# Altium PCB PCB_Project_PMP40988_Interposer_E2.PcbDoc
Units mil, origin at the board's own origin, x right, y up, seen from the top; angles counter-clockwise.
Board outline 2755.91 x 2165.35 mil, 2 copper layers (Top Layer, Bottom Layer), stack 62 mil thick; 7 components, 34 nets, 208 pads, 25 vias.
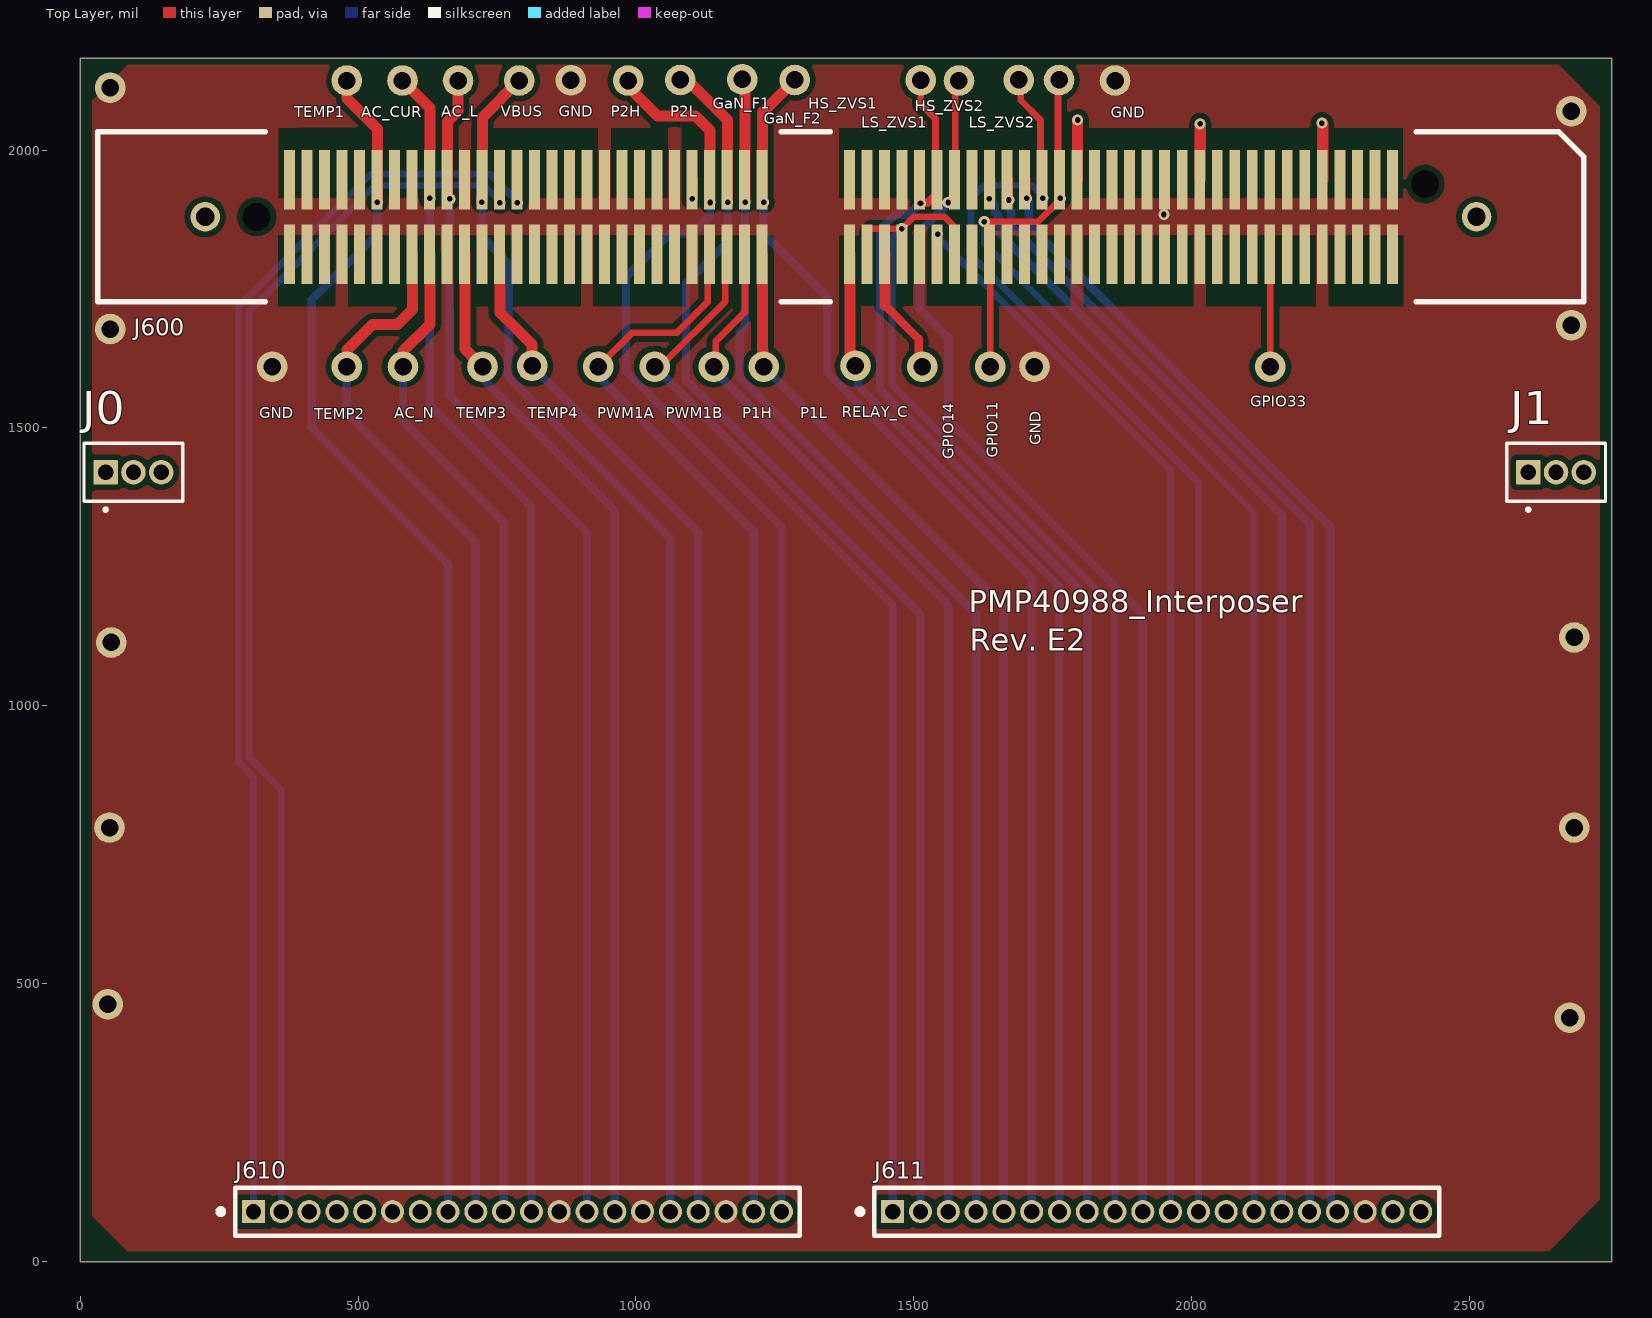
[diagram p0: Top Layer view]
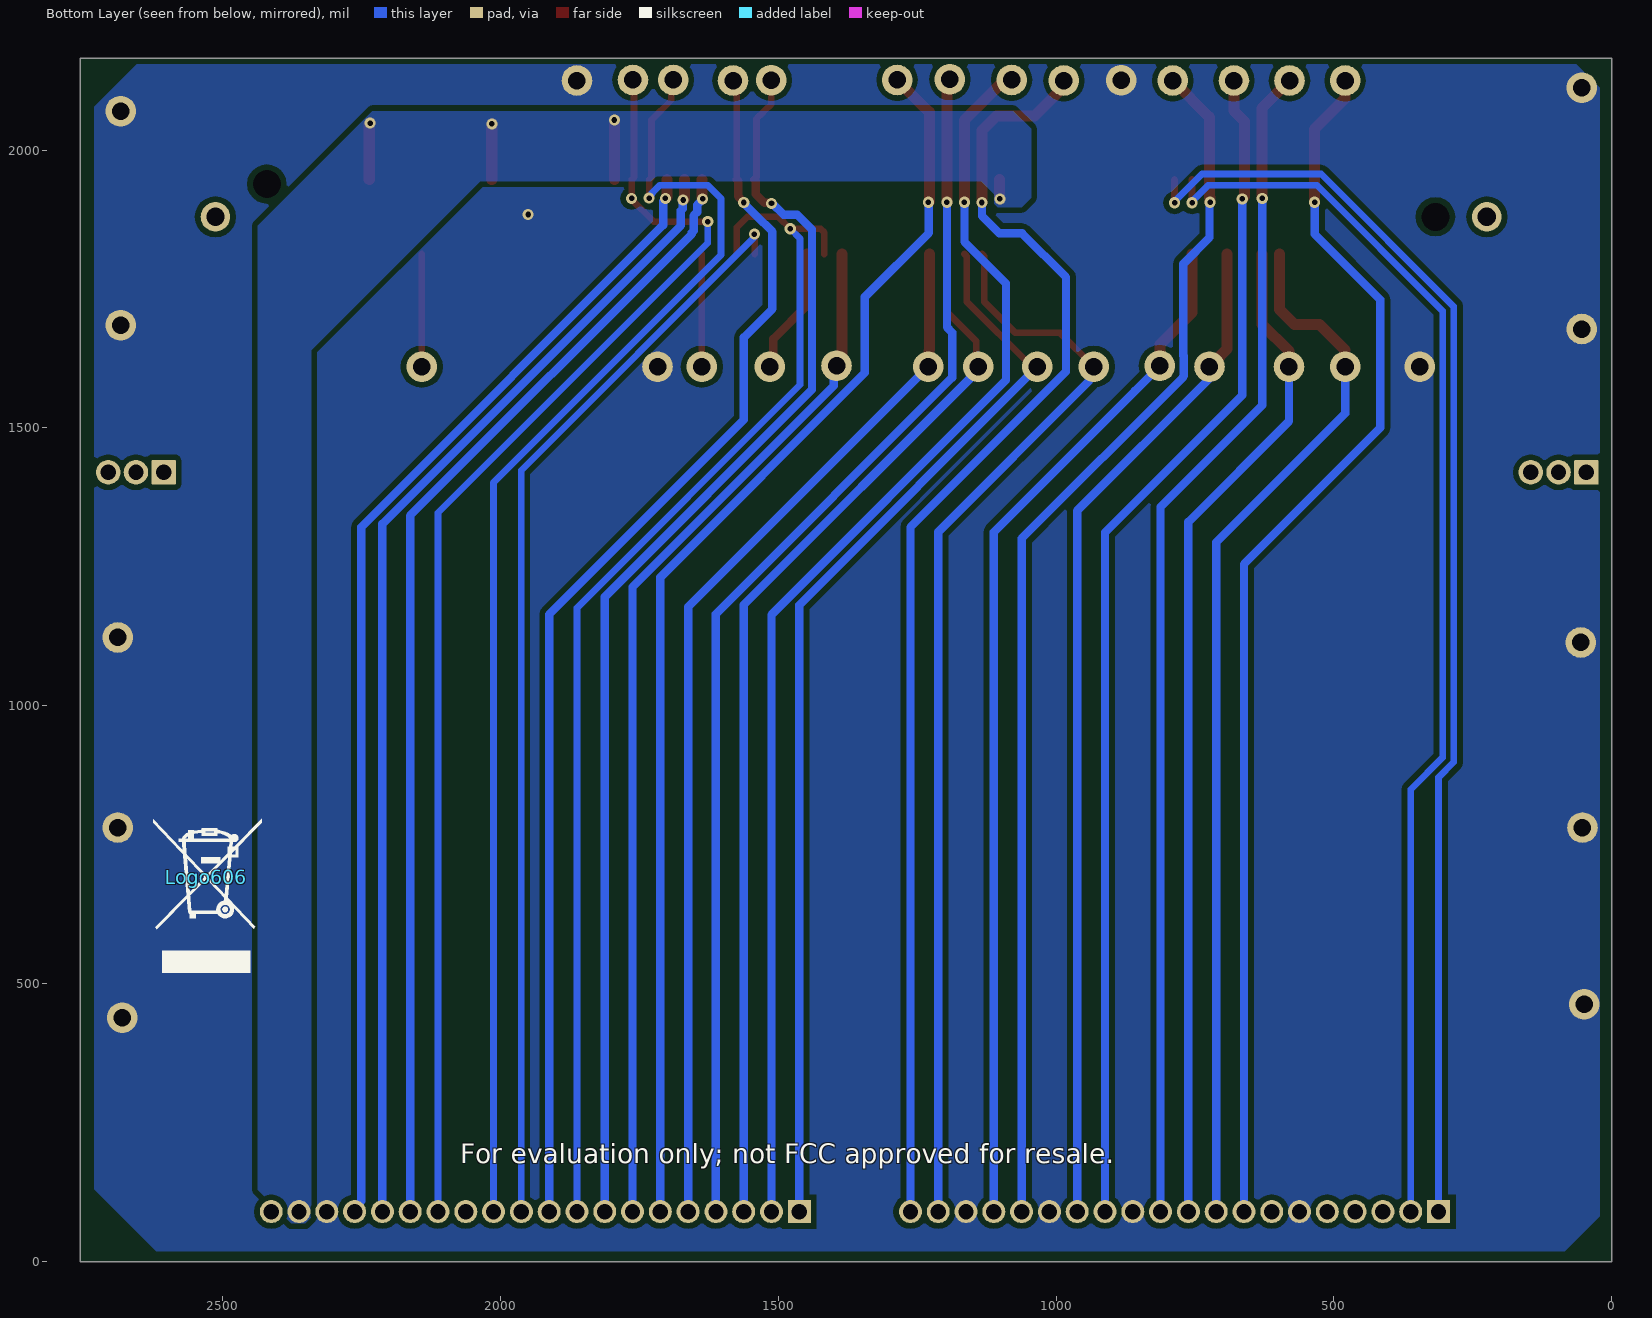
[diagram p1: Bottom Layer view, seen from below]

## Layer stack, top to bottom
Top Solder: solder mask 0.4, Solder Resist, Dk 3.5
Top Layer: signal copper 1.4
Dielectric1: core 59.2, FR-4 High Tg, Dk 4.8
Bottom Layer: signal copper 1.4
Bottom Solder: solder mask 0.4, Solder Resist, Dk 3.5

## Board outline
0,0 2755.91,0 2755.91,2165.35 0,2165.35

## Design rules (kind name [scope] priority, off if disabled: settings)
AcuteAngle [All] p1: minimum=4.50000000000000E+0001 checktracksonly=FALSE
AssemblyTestPointUsage [All] p1: valid=2
Clearance Clearance_3 [InNet('EARTH') vs Not InNet('EARTH') And Not InNet('12VS')] p1: gap=200 ignorepadtopadclearanceinfootprint=FALSE except(0: Arc-Hole Track-Hole SMDPad-Hole THPad-Hole Via-Hole Fill-Hole Poly-Hole Region-Hole Text-Hole)
Clearance Clearance_1 [InNetClass('HV') vs InNetClass('MV')] p2: gap=25 ignorepadtopadclearanceinfootprint=FALSE except(0: Arc-Hole Track-Hole SMDPad-Hole THPad-Hole Via-Hole Fill-Hole Poly-Hole Region-Hole Text-Hole)
Clearance Clearance_2 [InNetClass('HV') vs Not InNetClass('HV')] p3: gap=50 ignorepadtopadclearanceinfootprint=FALSE except(0: Arc-Hole Track-Hole SMDPad-Hole THPad-Hole Via-Hole Fill-Hole Poly-Hole Region-Hole Text-Hole)
Clearance Clearance_Keepouts [((IsTrack Or IsArc) And Not InPoly) And IsFree and IsKeepOut vs ((IsTrack Or IsArc) And Not InPoly) And IsFree and IsKeepOut] p4: gap=0 ignorepadtopadclearanceinfootprint=FALSE
Clearance Clearance_BoardEdge_MountingHoles [OnCopper and InComponentClass('Mounting Holes') vs IsKeepOut] p5: gap=40 ignorepadtopadclearanceinfootprint=FALSE except(0: Arc-Hole Track-Hole SMDPad-Hole THPad-Hole Via-Hole Fill-Hole Poly-Hole Region-Hole Text-Hole)
Clearance Clearance_BoardEdge_Poly [OnCopper and InPoly vs IsKeepOut] p6: gap=25 ignorepadtopadclearanceinfootprint=FALSE except(0: Arc-Hole Track-Hole SMDPad-Hole THPad-Hole Via-Hole Fill-Hole Poly-Hole Region-Hole Text-Hole)
Clearance Clearance_BoardEdge [OnCopper and Not InComponentClass('Logo') and not InComponentClass('FiducialMark') and not InRegion(1000,500,4000,800) and Not IsKeepout vs IsKeepOut] p7: gap=75 ignorepadtopadclearanceinfootprint=FALSE except(0: Arc-Hole Track-Hole SMDPad-Hole THPad-Hole Via-Hole Fill-Hole Poly-Hole Region-Hole Text-Hole)
Clearance Clearance_Poly [InPolygon] p8: gap=10 ignorepadtopadclearanceinfootprint=FALSE except(0: Arc-Hole Track-Hole SMDPad-Hole THPad-Hole Via-Hole Fill-Hole Poly-Hole Region-Hole Text-Hole)
Clearance [All] p9: gap=7.87 ignorepadtopadclearanceinfootprint=FALSE except(0: Arc-Hole Track-Hole SMDPad-Hole THPad-Hole Via-Hole Fill-Hole Poly-Hole Region-Hole Text-Hole)
ComponentClearance ComponentClearance_MountingHoles_FiducialMarks [InComponentClass('Mounting Holes') vs InComponentClass('FiducialMark')] p1: gap=20 collisioncheckmode=3 verticalgap=10 showdistances=FALSE
ComponentClearance ComponentClearance_Shunt [InComponentClass('Header') vs InComponentClass('Shunt')] p2: gap=0 collisioncheckmode=3 verticalgap=0 showdistances=FALSE
ComponentClearance ComponentClearance_Logo [InComponentClass('Logo')] p3: gap=5 collisioncheckmode=3 verticalgap=10 showdistances=FALSE
ComponentClearance ComponentClearance_ScrewToNut [(HasFootprint('NY PMS 440 0025 PH')) vs (HasFootprint('Keystone_1902C'))] p4: gap=20 collisioncheckmode=3 verticalgap=100000 showdistances=FALSE
ComponentClearance ComponentClearance_MountingHoles [InComponentClass('Mounting Holes')] p5: gap=20 collisioncheckmode=3 verticalgap=10 showdistances=FALSE
ComponentClearance ComponentClearance_SmallPassives [HasFootprint('0201*') or HasFootprint('0402*') or HasFootprint('0508') or HasFootprint('0603*') or HasFootprint('0612') or HasFootprint('0805*') or HasFootprint('0815*') or HasFootprint('0830*') or HasFootprint('1206*') or HasFootprint('1210*') or HasFootprint('1808*') or HasFootprint('1812*') or HasFootprint('1825*') or HasFootprint('2010*') or HasFootprint('2220*') or HasFootprint('2225*') or HasFootprint('2512*') or HasFootprint('2728*') or HasFootprint('3518*') vs HasFootprint('0201*') or HasFootprint('0402*') or HasFootprint('0508') or HasFootprint('0603*') or HasFootprint('0612') or HasFootprint('0805*') or HasFootprint('0815*') or HasFootprint('0830*') or HasFootprint('1206*') or HasFootprint('1210*') or HasFootprint('1808*') or HasFootprint('1812*') or HasFootprint('1825*') or HasFootprint('2010*') or HasFootprint('2220*') or HasFootprint('2225*') or HasFootprint('2512*') or HasFootprint('2728*') or HasFootprint('3518*')] p6: gap=20 collisioncheckmode=3 verticalgap=20 showdistances=FALSE
ComponentClearance ComponentClearance_THtoSMT [IsThruComponent vs IsSMTComponent] p7: gap=10 collisioncheckmode=3 verticalgap=10 showdistances=FALSE
ComponentClearance ComponentClearance_THtoTH [IsThruComponent vs IsThruComponent] p8: gap=10 collisioncheckmode=3 verticalgap=10 showdistances=FALSE
ComponentClearance [All] p9: gap=10 collisioncheckmode=3 verticalgap=10 showdistances=FALSE
DiffPairsRouting [All] p1: maxlimit=100 minlimit=10 mostfreqgap=10 toplayer_minwidth=15 toplayer_maxwidth=15 toplayer_prefwidth=15 bottomlayer_minwidth=15 bottomlayer_maxwidth=15 bottomlayer_prefwidth=15 maxuncoupledlength=1000
FabricationTestPointUsage TestPointUsage [All] p1: valid=2 allowmultiple=FALSE
FabricationTestpoint Testpoint [All] p1: side=3 testpointundercomponent=TRUE minsize=40 maxsize=100 preferedsize=60 minholesize=0 maxholesize=40 preferedholesize=32 testpointgrid=1 allowsidetop=TRUE allowsidebottom=TRUE usegrid=TRUE gridtolerance=0.01
FanoutControl Fanout_LCC [IsLCC] p1: bgadir=Out bgaviamode=Centered fanoutstyle=Auto fanoutdirection=Alternating viagrid=1 // Fanout_LCC (Default Rule)
FanoutControl Fanout_BGA [IsBGA] p2: bgadir=Out bgaviamode=Centered fanoutstyle=Auto fanoutdirection=Alternating viagrid=1 // Fanout_BGA (Default Rule)
FanoutControl Fanout_Default [All] p4: bgadir=Out bgaviamode=Centered fanoutstyle=Auto fanoutdirection=Alternating viagrid=1 // Fanout_Default (Default Rule)
FanoutControl Fanout_Small [(CompPinCount < 5)] p5: bgadir=Out bgaviamode=Centered fanoutstyle=Auto fanoutdirection=OutThenIn viagrid=1 // Fanout_Small (Default Rule)
Height [All] p1: minheight=0 maxheight=3000 prefheight=500
HoleSize [All] p1: absolutevalues=TRUE maxlimit=251 minlimit=7 maxpercent=80.000 minpercent=20.000
MinimumAnnularRing MinimumAnnularRing_ThermalPadVias [IsVia and InAnyComponent] p1: minimumring=5.91
MinimumAnnularRing [All] p2: minimumring=4.9
MinimumSolderMaskSliver MinimumSolderMaskSliver_Logo [InComponentClass('Logo') vs InComponentClass('Logo')] p1: minsoldermaskwidth=0.7
MinimumSolderMaskSliver [All] p2: minsoldermaskwidth=2
PlaneConnect [All] p1: planeconnectstyle=Direct reliefexpansion=10 reliefentries=4 reliefconductorwidth=10 reliefairgap=10
PolygonConnect [All] p1: connectstyle=Direct reliefconductorwidth=10 reliefentries=4 polygonreliefangle="90 Angle" airgapwidth=10
RoutingVias ThermalPadVias [IsVia and InAnyComponent] p1: holewidth=7.87 width=19.68 viastyle="Through Hole" minholewidth=7.87 minwidth=19.68 maxholewidth=12.99 maxwidth=23.62
RoutingVias [All] p2: holewidth=16 width=34 viastyle="Through Hole" minholewidth=7.87 minwidth=20 maxholewidth=40 maxwidth=65
SilkToBoardRegionClearance [Not ((IsComment or IsDesignator) And (Hide <> 'False')) and not InRegion(1000,500,4000,800)] p1:
SilkToSilkClearance SilkToSilkClearance_Pb-FreeLogo [(HasFootprint('Pb-Free_Overlay_Medium') OR HasFootprint('Pb-Free_Overlay_Small')) vs (HasFootprint('Pb-Free_Overlay_Medium') OR HasFootprint('Pb-Free_Overlay_Small'))] p1: silktosilkclearance=0
SilkToSilkClearance [All] p2: silktosilkclearance=1
SilkToSolderMaskClearance "Silk to Solder Mask Opening" [All] p1: minsilkscreentomaskgap=1 clearancetoexposedcopper=FALSE
SolderMaskExpansion [All] p1: expansion=1.97 istentingtop=FALSE
Width [All] p1: maxlimit=100 minlimit=6 preferedwidth=10 checkconnectedcopper=TRUE
14 further rules are at their usual default settings.

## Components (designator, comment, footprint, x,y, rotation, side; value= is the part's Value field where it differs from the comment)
J0 "M52-5000345" FP-M52-5000345_HDR3-MFG 96,1420 r0 top
J1 "M52-5000345" FP-M52-5000345_HDR3-MFG 2655.41,1420 r0 top
J600 "HSEC8-160-01-L-DV-A-BL" controlCARD-120HSEC 1296.12,1878.84 r0 top
J610 "M52-5002045" M52-5002045 312,90 r0 top
J611 "M52-5002045" M52-5002045 1462,90 r0 top
Logo605 "FCC disclaimer" FCC_disclaimer 1340,-308 r180 bottom
Logo606 "WEEE logo" WEEE_Minimum 2528.92,692 r180 bottom

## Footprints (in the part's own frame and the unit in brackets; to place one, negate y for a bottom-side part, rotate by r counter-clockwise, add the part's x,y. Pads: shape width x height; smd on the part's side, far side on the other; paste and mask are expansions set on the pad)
controlCARD-120HSEC [mm] "Pads are not numbered according to Samtec datasheet."
  rect 0.5x2.724 smd: 1(-23.357,-1.678) 2(-23.357,1.722) 3(-22.557,-1.678) 4(-22.557,1.722) 5(-21.757,-1.678) 6(-21.757,1.722) 7(-20.957,-1.678) 8(-20.957,1.722) 9(-20.157,-1.678) 10(-20.157,1.722) 11(-19.357,-1.678) 12(-19.357,1.722) 13(-18.557,-1.678) 14(-18.557,1.722) 15(-17.757,-1.678) 16(-17.757,1.722) 17(-16.957,-1.678) 18(-16.957,1.722) 19(-16.157,-1.678) 20(-16.157,1.722) 21(-15.357,-1.678) 22(-15.357,1.722) 23(-14.557,-1.678) 24(-14.557,1.722) 25(-13.757,-1.678) 26(-13.757,1.722) 27(-12.957,-1.678) 28(-12.957,1.722) 29(-12.157,-1.678) 30(-12.157,1.722) 31(-11.357,-1.678) 32(-11.357,1.722) 33(-10.557,-1.678) 34(-10.557,1.722) 35(-9.757,-1.678) 36(-9.757,1.722) 37(-8.957,-1.678) 38(-8.957,1.722) 39(-8.157,-1.678) 40(-8.157,1.722) 41(-7.357,-1.678) 42(-7.357,1.722) 43(-6.557,-1.678) 44(-6.557,1.722) 45(-5.757,-1.678) 46(-5.757,1.722) 47(-4.957,-1.678) 48(-4.957,1.722) 49(-4.157,-1.678) 50(-4.157,1.722) 51(-3.357,-1.678) 52(-3.357,1.722) 53(-2.557,-1.678) 54(-2.557,1.722) 55(-1.757,-1.678) 56(-1.757,1.722) 57(2.243,-1.678) 58(2.243,1.722) 59(3.043,-1.678) 60(3.043,1.722) 61(3.843,-1.678) 62(3.843,1.722) 63(4.643,-1.678) 64(4.643,1.722) 65(5.443,-1.678) 66(5.443,1.722) 67(6.243,-1.678) 68(6.243,1.722) 69(7.043,-1.678) 70(7.043,1.722) 71(7.843,-1.678) 72(7.843,1.722) 73(8.643,-1.678) 74(8.643,1.722) 75(9.443,-1.678) 76(9.443,1.722) 77(10.243,-1.678) 78(10.243,1.722) 79(11.043,-1.678) 80(11.043,1.722) 81(11.843,-1.678) 82(11.843,1.722) 83(12.643,-1.678) 84(12.643,1.722) 85(13.443,-1.678) 86(13.443,1.722) 87(14.243,-1.678) 88(14.243,1.722) 89(15.043,-1.678) 90(15.043,1.722) 91(15.843,-1.678) 92(15.843,1.722) 93(16.643,-1.678) 94(16.643,1.722) 95(17.443,-1.678) 96(17.443,1.722) 97(18.243,-1.678) 98(18.243,1.722) 99(19.043,-1.678) 100(19.043,1.722) 101(19.843,-1.678) 102(19.843,1.722) 103(20.643,-1.678) 104(20.643,1.722) 105(21.443,-1.678) 106(21.443,1.722) 107(22.243,-1.678) 108(22.243,1.722) 109(23.043,-1.678) 110(23.043,1.722) 111(23.843,-1.678) 112(23.843,1.722) 113(24.643,-1.678) 114(24.643,1.722) 115(25.443,-1.678) 116(25.443,1.722) 117(26.243,-1.678) 118(26.243,1.722) 119(27.043,-1.678) 120(27.043,1.722)
  round 0.025 hole 1.27 unplated mask+0.876: 181(-24.857,0.022) 182(28.543,1.522)
  round 1.348 hole 0.84: 185(-27.207,0.022) 186(30.893,0.022)
  silkscreen extent -32.11,-3.86 35.8,3.9, body extent -31.75,-3.48 35.3,3.52, height 12.35
FCC_disclaimer [mil]
FP-M52-5000345_HDR3-MFG [mm]
  rrect9% 1.12x1.12 hole 0.7 paste-1000 mask+0: 1(-1.27,0)
  round 1.12 hole 0.7 paste-1000 mask+0: 2(0,0) 3(1.27,0)
  silkscreen extent -2.25,-1.77 2.25,1.33, body extent -2.35,-1.43 2.35,1.43, height 0.25
M52-5002045 [mm] "CONN RCPT 20POS 0.05 GOLD PCB"
  rect 1.05x1.05 hole 0.7: 1(0,0)
  round 1.05 hole 0.7: 2(1.27,0) 3(2.54,0) 4(3.81,0) 5(5.08,0) 6(6.35,0) 7(7.62,0) 8(8.89,0) 9(10.16,0) 10(11.43,0) 11(12.7,0) 12(13.97,0) 13(15.24,0) 14(16.51,0) 15(17.78,0) 16(19.05,0) 17(20.32,0) 18(21.59,0) 19(22.86,0) 20(24.13,0)
  silkscreen extent -1.6,-1.1 24.97,1.1, body extent -0.84,-1.1 24.97,1.1, height 4.1
WEEE_Minimum [mil] "WEEElie bin"
  silkscreen extent -95,-172 99,104

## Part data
J0 J1: library part CMP-0097095-1, "3 Position Receptacle Connector 0.050\" (1.27mm) Through Hole Gold", Current_A=1A, Digikey Part Number=952-3357-ND, Manufacturer=Harwin, Mouser Part Number=855-M52-5000345, Operating Temperature Range="-40°C to +105°C"
J600: library part CMP-0003814-2, "C2000 controlCARD-120HSEC connector, SMT", Manufacturer=Samtec
J610 J611: library part Receptacle_20x1, "Receptacle, 20x1, 1.27mm, TH", Manufacturer="Harwin Inc.", Supplier Part Number 1=952-1903-ND
Logo605: library part CMP-0074847-1, "FCC_disclaimer"
Logo606: library part CMP-0074769-1

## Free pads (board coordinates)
  round 55.12 hole 31.5: 1(50,463) 1(52.94,781) 1(54,1677.88) 1(54,2112) 1(56,1114) 1(346,1610.21) 1(480,1610.21) 1(480,2125) 1(580,2125) 1(581,1610.21) 1(680,2125) 1(724,1610.21) 1(790,2125) 1(813.21,1611.6) 1(883,2125.35) 1(932.12,1610.21) 1(986,2125) 1(1034,1610.21) 1(1080,2126) 1(1140.06,1610.21) 1(1191,2127) 1(1229.84,1610.21) 1(1286,2126) 1(1395,1612) 1(1512.6,2125.67) 1(1515.23,1610.21) 1(1581.2,2125) 1(1637.28,1610.21) 1(1688.58,2126) 1(1717,1610.21) 1(1761.25,2126) 1(1862,2125) 1(2141.21,1610.21) 1(2680,439) 1(2683,1685) 1(2683,2070) 1(2688,781) 1(2688,1123)

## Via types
v1: diameter 20, hole 10, Top Layer to Bottom Layer, 25 vias

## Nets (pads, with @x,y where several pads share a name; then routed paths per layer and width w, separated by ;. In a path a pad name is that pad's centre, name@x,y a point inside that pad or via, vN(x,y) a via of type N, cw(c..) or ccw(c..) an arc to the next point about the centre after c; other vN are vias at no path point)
5Vp: J600.48 J600.84 J600.98 J600.112 J611.19 | length 344.8
  Top Layer w20: v1(1101,1912) 1101.68,1912.68 1101.68,1946.64 J600.48@1101.84,1946.8 ; J600.84@1794.76,1946.8 v1(1794.76,2053.96) ; v1(2015,2047) 2015.23,2046.77 J600.98@2015.23,1946.8 ; v1(2234,2048.3) 2235.7,2046.6 J600.112@2235.7,1946.8
AC_CUR_G: J600.18 J610.11 pad.1@580,2125 | length 2131.4
  Top Layer w20: pad.1@580,2125 629.4,2075.6 629.4,1946.8 629.4,1913.4 v1(629,1913)
  Bottom Layer w15: v1(629,1913) 629,1541 812,1358 J610.11
ACL_SENSE: J600.20 J610.13 pad.1@680,2125 | length 2146.9
  Top Layer w20: v1(665,1912) 660.9,1916.1 660.9,1946.8 660.9,2050.9 680,2070 pad.1@680,2125
  Bottom Layer w15: v1(665,1912) 665,1559 912,1312 J610.13
ACN_SENSE: J600.17 J610.10 pad.1@581,1610.21 | length 1790.2
  Top Layer w20: 581,1638 629.4,1686.4 J600.17@629.4,1812.94
  Bottom Layer w15: pad.1@581,1610.21 581,1512 762,1331 J610.10
ADC_SENSE: J600.28 J610.1 | length 2305
  Top Layer w12: v1(786.88,1905.2) J600.28@786.88,1946.8
  Bottom Layer w12: J610.1 312,871.23 284.69,898.54 284.69,1718.56 522.88,1956.75 737.6,1956.75 785.35,1908.99 785.35,1906.73 v1(786.88,1905.2)
DC_SENSE: J600.24 J610.16 pad.1@790,2125 | length 2203.8
  Top Layer w20: v1(723,1906) 723,1914 723.89,1914.89 723.89,1946.8 723.89,2058.89 pad.1@790,2125
  Bottom Layer w15: v1(723,1906) 723.96,1905.04 723.96,1842.47 771.06,1795.36 771.06,1630.17 770.28,1629.39 770.28,1593.82 771.06,1593.04 771.06,1591.94 1062,1301 J610.16
GaN_F1: J600.54 J611.4 pad.1@1191,2127 | length 2219.2
  Top Layer w20: pad.1@1191,2127 1196.33,2121.67 v1(1196.33,1906)
  Bottom Layer w15: v1(1196.33,1906) 1196.33,1681.1 1186.91,1671.68 1186.91,1590.31 1612,1165.22 J611.4
GaN_F2: J600.56 J611.6 pad.1@1286,2126 | length 2261.3
  Top Layer w20: v1(1229.84,1906) 1227.98,1907.86 1227.98,1946.64 1227.83,1946.8 1227.83,2067.83 pad.1@1286,2126
  Bottom Layer w15: v1(1229.84,1906) 1229,1905.16 1229,1851 1344,1736 1344,1599.35 1712,1231.35 J611.6
GPIO11: J600.73 pad.1@1637.28,1610.21 | length 174.9
  Top Layer w12: 1637.28,1638 J600.73@1637.28,1812.94
GPIO14: J600.61 pad.1@1515.23,1610.21 | length 230.4
  Top Layer w15: 1448.3,1720.7 1508.73,1660.27 1508.73,1616.72 pad.1@1515.23,1610.21
  Top Layer w20: 1448.3,1720.7 J600.61@1448.3,1812.94
GPIO33: J600.105 pad.1@2141.21,1610.21 | length 172.9
  Top Layer w12: 2141.21,1640 J600.105@2141.21,1812.94
HS_ZVS1: J600.68 J611.8 pad.1@1512.6,2125.67 | length 2268
  Top Layer w12: pad.1@1512.6,2125.67 1512.6,2087.65 1512.58,2087.03 1512.58,2082.06 1516.09,2078.54 1519.52,2075.12 1520.03,2075.12 1531.92,2063.24 1533.49,2062.21 cw(c1526.94,2052.15) 1536.52,2059.39 1538.94,2056.21 1538.94,1950.64 J600.68@1542.79,1946.8
  Top Layer w15: v1(1512,1904.05) 1512.96,1905.01 1524.71,1905.01 1540.44,1920.74 1540.44,1944.45 J600.68@1542.79,1946.8
  Bottom Layer w15: v1(1512,1904.05) 1510.65,1904.05 1490.36,1883.76 1465.72,1883.76 1439.25,1857.3 1439.25,1568.79 1812,1196.05 J611.8
HS_ZVS2: J600.80 J611.12 pad.1@1688.58,2126 | length 2374.5
  Top Layer w12: pad.1@1688.58,2126 1692.45,2122.13 1692.45,2089.44 1727.92,2053.96 1727.92,1950.64 1731.76,1946.8 1732,1946.56 1732,1913.57 v1(1732.24,1913.33)
  Bottom Layer w12: v1(1732.24,1913.33) 1732.24,1915.5 1726.87,1920.86 1726.87,1922.89 1712.89,1936.87 1627.11,1936.87 1602.88,1912.64 1602.88,1811.04 2012,1401.91 J611.12
LS_ZVS1: J600.70 J611.10 pad.1@1581.2,2125 | length 2230.7
  Top Layer w12: J600.70@1574.28,1946.8 1574.28,2118.09 pad.1@1581.2,2125
  Top Layer w15: v1(1562,1905.5) 1562,1906.85 1571.94,1916.79 1571.94,1944.45 J600.70@1574.28,1946.8
  Bottom Layer w15: v1(1562,1905.5) 1562,1904.8 1539.51,1882.3 1510.41,1853.21 1510.41,1714.13 1561.63,1662.91 1561.63,1514.83 1912,1164.46 J611.10
LS_ZVS2: J600.82 J611.14 pad.1@1761.25,2126 | length 2352.7
  Top Layer w12: v1(1626.75,1871.21) 1723.88,1871.21 1763.74,1911.06 v1(1763.74,1912.92) 1763.5,1913.16 1763.5,1946.56 1763.26,1946.8 1759.42,1950.64 1759.42,2119.03 pad.1@1761.25,2126
  Bottom Layer w12: v1(1626.75,1871.21) 1626.75,1832.72 2112,1347.47 J611.14
PFCG_1H: J600.53 J611.3 pad.1@1140.06,1610.21 | length 1961.9
  Top Layer w12: pad.1@1140.06,1610.21 1143.45,1613.6 1143.45,1655.77 1196.33,1708.66 J600.53@1196.33,1812.94
  Top Layer w20: pad.1@1140.06,1610.21 pad.1@1140.06,1619.72
  Bottom Layer w15: pad.1@1140.06,1630.3 pad.1@1149.88,1618.16 ; pad.1@1153.99,1604.88 1149.68,1609.19 1144.4,1609.75 1140.06,1610.21 1140.06,1603.73 1562,1181.79 J611.3
PFCG_1L: J600.55 J611.5 pad.1@1229.84,1610.21 | length 1965.2
  Top Layer w20: 1227.83,1732.17 1227.83,1812.94 1227.67,1812.78 1227.67,1643.47 pad.1@1229.84,1627.91
  Bottom Layer w15: pad.1@1229.84,1610.21 1662,1178.06 J611.5
PFCG_2H: J600.50 J610.20 pad.1@986,2125 | length 2337
  Top Layer w20: pad.1@986,2125 986,2114 1039,2061 1107,2061 1133.34,2034.66 v1(1133.34,1905.5)
  Bottom Layer w15: v1@1133.34,1904.15 1133.34,1881.34 1102,1850 1061,1850 982.21,1771.21 982.21,1601.29 991.07,1592.43 1262,1321.5 J610.20
PFCG_2L: J600.52 J611.2 pad.1@1080,2126 | length 2284.5
  Top Layer w20: pad.1@1080,2126 1092.83,2126 1164.83,2054 v1(1164.83,1906)
  Bottom Layer w15: v1(1164.83,1906) 1164.83,1834.83 1090,1760 1090,1585.88 1512,1163.88 J611.2
PGND: J600.7 J600.19 J600.22 J600.35 J600.38 J600.46 J600.47 J600.65 J600.83 J600.97 J600.111 J610.6 J610.12 J610.15 J610.18 J611.18 pad.1@50,463 pad.1@52.94,781 pad.1@54,1677.88 pad.1@54,2112 pad.1@56,1114 pad.1@346,1610.21 pad.1@883,2125.35 pad.1@1717,1610.21 pad.1@1862,2125 pad.1@2680,439 pad.1@2683,1685 pad.1@2683,2070 pad.1@2688,781 pad.1@2688,1123
  other v1: 1950,1884
PRI_FAULT: J600.74 J611.15 | length 2073.8
  Top Layer w20: v1(1636,1912) 1637.28,1913.28 J600.74@1637.28,1946.8
  Bottom Layer w15: v1@1636.96,1911.04 1636.96,1909.69 1645.63,1901.02 1645.63,1888.22 1652.13,1881.72 1652.13,1854.82 1655.23,1851.71 1655.23,1848.98 2162,1342.21 J611.15
PWM1A: J600.49 J610.19 pad.1@932.12,1610.21 | length 1969.1
  Top Layer w12: pad.1@932.12,1610.21 992.92,1671.02 1073.01,1671.02 1129.5,1727.51 1129.5,1809.09 J600.49@1133.34,1812.94
  Bottom Layer w15: pad.1@932.12,1610.21 939.79,1602.54 939.79,1585.21 1212,1313 J610.19
PWM1B: J600.51 J611.1 pad.1@1034,1610.21 | length 1960.1
  Top Layer w12: pad.1@1034,1610.21 1043.7,1610.21 1160.99,1727.51 1160.99,1809.09 J600.51@1164.83,1812.94
  Bottom Layer w15: pad.1@1034,1610.21 1034,1609.53 1462,1181.53 J611.1
RELAY_CTRL: J600.57 J611.7 pad.1@1395,1612 | length 1879.4
  Top Layer w20: J600.57@1385.31,1812.94 1385.31,1628.27 pad.1@1397.67,1611.6
  Bottom Layer w15: pad.1@1395,1612 1399.75,1607.25 1399.75,1575.95 1762,1213.7 J611.7
SCI_RX0: J600.76 J611.16 | length 2081.8
  Top Layer w20: J600.76@1668.77,1946.8 1668.77,1912.23 v1(1671,1910)
  Bottom Layer w15: v1(1671,1910) 1671.96,1909.04 1671.96,1894.24 1675,1891.19 1675,1864.29 2212,1327.29 J611.16
SCI_TX0: J600.78 J611.17 | length 2089.5
  Top Layer w20: J600.78@1700.27,1946.8 1700.27,1915.73 v1(1703,1913)
  Bottom Layer w15: v1(1703,1913) 1703,1911.65 1706.87,1907.78 1706.87,1864.77 2250,1321.64 2250,109.13 2262,97.13 J611.17
SDC: J600.59 J600.69 J611.9 | length 2205.4
  Top Layer w12: J600.59@1416.8,1812.94 1416.8,1851.36 1423.83,1858.39 v1(1478.31,1858.39) 1499.59,1879.67 1555.58,1879.67 1574.28,1860.96 J600.69@1574.28,1812.94
  Bottom Layer w12: v1(1478.31,1858.39) 1460.63,1840.71 1460.63,1577.65 1862,1176.27 J611.9
SDD: J600.67 J611.11 | length 1968.8
  Top Layer w12: J600.67 1542.35,1813.22 1542.35,1848.36 v1(1542.79,1848.8)
  Bottom Layer w12: v1(1542.79,1848.8) 1544.32,1847.27 1544.32,1841.49 1962,1423.81 J611.11
TEMP1: J600.12 J610.8 pad.1@480,2125 | length 2208.1
  Top Layer w20: pad.1@480,2125 480,2093 534.91,2038.09 v1(534.91,1906)
  Bottom Layer w15: v1(534.91,1906) 534.91,1848.91 417,1731 417,1500 662,1255 J610.8
TEMP2: J600.15 J610.9 pad.1@480,1610.21 | length 1864.4
  Top Layer w20: 480,1640 526,1686 571,1686 597.91,1712.91 J600.15@597.91,1812.94
  Bottom Layer w15: pad.1@480,1610.21 480,1526 712,1294 J610.9
TEMP3: J600.21 J610.14 pad.1@724,1610.21 | length 1787.5
  Top Layer w20: J600.21@692.39,1812.94 692.39,1641.82 pad.1@704.7,1629.51
  Bottom Layer w15: pad.1@723,1609.21 pad.1@724,1610.21 ; pad.1@724,1589 962,1351 J610.14
TEMP4: J600.25 J610.17 pad.1@813.21,1611.6 | length 1870.7
  Top Layer w20: J600.25@755.39,1812.94 755.39,1707.61 813.21,1649.79 pad.1@813.21,1611.6
  Bottom Layer w15: pad.1@813.21,1611.6 858.16,1566.65 1112,1312.82 J610.17
Vcb_SENSE: J600.26 J610.2 | length 2244.8
  Top Layer w12: v1(755.39,1905.2) J600.26@755.39,1946.8
  Bottom Layer w12: J610.2 362,849.33 304.57,906.77 304.57,1710.33 531.11,1936.87 725.89,1936.87 753.86,1908.91 753.86,1906.73 v1(755.39,1905.2)
VREFHI: J600.45
pads on no net: J0.1 J0.2 J0.3 J1.1 J1.2 J1.3 J600.1 J600.2 J600.3 J600.4 J600.5 J600.6 J600.8 J600.9 J600.10 J600.11 J600.13 J600.14 J600.16 J600.23 J600.27 J600.29 J600.30 J600.31 J600.32 J600.33 J600.34 J600.36 J600.37 J600.39 J600.40 J600.41 J600.42 J600.43 J600.44 J600.58 J600.60 J600.62 J600.63 J600.64 J600.66 J600.71 J600.72 J600.75 J600.77 J600.79 J600.81 J600.85 J600.86 J600.87 J600.88 J600.89 J600.90 J600.91 J600.92 J600.93 J600.94 J600.95 J600.96 J600.99 J600.100 J600.101 J600.102 J600.103 J600.104 J600.106 J600.107 J600.108 J600.109 J600.110 J600.113 J600.114 J600.115 J600.116 J600.117 J600.118 J600.119 J600.120 J600.181 J600.182 J600.185 J600.186 J610.3 J610.4 J610.5 J610.7 J611.13 J611.20

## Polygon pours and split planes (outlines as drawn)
PGND on Bottom Layer "Top Layer-No Net" (solid, remove dead copper, pour order 4): 2654,2154 2730,2078 2730,130 2619,19 85,19 22,82 22,2112 64,2154
5Vp on Bottom Layer "Bottom Layer-No Net" (solid, pour order 0): 1111,1903 1111,1920 1135,1944 2036,1944 2340,1640 2340,108 2340,80 2351,69 2376,69 2436,129 2436,1864 2230,2070 1077,2070 1045,2038 1045,1914 1062,1897 1105,1897
PGND on Top Layer "Top Layer-No Net" (solid, remove dead copper, pour order 2): 2660,2153 2734,2079 2734,111 2642,19 85,19 22,82 22,2089 86,2153

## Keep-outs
Keep-Out Layer:
  text ".Layer_Name" at -945,-1745.76 h60

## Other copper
Top Layer:
  text ".Layer_Name" at -945,-1745.76 h60
Bottom Layer:
  text ".Layer_Name" at -945,-1745.76 h60

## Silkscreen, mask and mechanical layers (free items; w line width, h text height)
Top Overlay:
  text "GaN_F1" at 1138,2074 h20
  text "HS_ZVS1" at 1310,2074 h20
  text "HS_ZVS2" at 1502,2070 h20
  text "AC_L" at 650,2060 h20
  text "VBUS" at 757,2060 h20
  text "GND" at 861,2060 h20
  text "P2H" at 955,2060 h20
  text "P2L" at 1062,2060 h20
  text "TEMP1" at 385,2059 h20
  text "AC_CUR" at 506,2059 h20
  text "GND" at 1854,2058 h20
  text "GaN_F2" at 1230,2047 h20
  text "LS_ZVS1" at 1405,2040 h20
  text "LS_ZVS2" at 1599,2040 h20
  text "GPIO33" at 2105,1538 h20
  text "RELAY_C" at 1369.92,1519.38 h20
  text "GND" at 322,1517 h20
  text "AC_N" at 565,1517 h20
  text "TEMP3" at 677,1517 h20
  text "TEMP4" at 805,1517 h20
  text "PWM1A" at 930,1517 h20
  text "PWM1B" at 1054,1517 h20
  text "P1H" at 1191,1517 h20
  text "P1L" at 1296,1517 h20
  text "TEMP2" at 421,1516 h20
  text "GND" at 1728,1469 h20 r90
  text "GPIO11" at 1650.64,1446.53 h20 r90
  text "GPIO14" at 1571.48,1444 h20 r90
  text "PMP40988_Interposer" at 1599,1168 h40
  text "Rev. E2" at 1600.68,1099 h40
  text ".Layer_Name" at -945,-1745.76 h60
Bottom Overlay:
  text ".Layer_Name" at -945,-1745.76 h60
Top Paste:
  text ".Layer_Name" at -945,-1745.76 h60
Bottom Paste:
  text ".Layer_Name" at -945,-1745.76 h60
Top Solder:
  text ".Layer_Name" at -945,-1745.76 h60
  text ".Layer_Name" at -945,-1745.76 h60
Bottom Solder:
  text ".Layer_Name" at -945,-1745.76 h60
Drill Guide:
  text ".Layer_Name" at -945,-1745.76 h60
M1 Board Outline:
  the board outline again, w7
  text ".Layer_Name" at -945,-1745.76 h60
M2 Board Dimensions:
  rectangle: -1522,-1162.27 -1397,-1037.27
  rectangle: -1397,-1287.27 -1022,-1162.27
  lines w7: -1522,-1162.27 -522,-1162.27 ; -1397,-1287.27 -1397,-1037.27 ; -1272,-1287.27 -1272,-1037.27 ; -1022,-1287.27 -1022,-1037.27 ; -772,-1287.27 -772,-1037.27 ; -1522,-1287.27 -522,-1287.27 -522,-1037.27 -1522,-1037.27 -1522,-1287.27
  text ".Layer_Name" at -945,-1745.76 h60
M3 3D STEP Top:
  text ".Layer_Name" at -945,-1745.76 h60
M4 3D STEP Bottom:
  text ".Layer_Name" at -945,-1745.76 h60
M5 Assembly Top:
  lines w10: -1814,-1817.43 4786,-1817.43 ; -1814,-1614.1 4788,-1614.1 ; -1814,-1410.77 -1814,-2020.77 2191,-2020.77 4788,-2020.77 4788,-1410.77 -1813.5,-1410.77 -1813.5,-2020.77 -238,-2020.77 ; 651,-2020.77 651,-1410.77 ; 1918,-1614.1 1918,-1410.77 ; 2758,-1614.1 2758,-1410.77 ; 3380,-2027.27 3380,-1824.43
  text "COMPONENTS MARKED 'DNP' SHOULD NOT BE POPULATED." at -368.5,-1205.77 h60
  text "ASSEMBLY VARIANT:" at -369,-1321.27 h60
  text ".VariantName" at 667,-1321.27 h60
  text "PCB VIEWED FROM TOP SIDE" at -1750.5,-1542.93 h60
  text "BOARD #:" at 726,-1542.93 h60
  text ".PRJ_Number" at 1271.5,-1542.93 h60
  text "REV:" at 2116,-1542.93 h60
  text ".PCB_Rev" at 2407.5,-1542.93 h60
  text "SVN REV:" at 2954,-1542.93 h60
  text ".VersionControl_RevNumber" at 3460,-1542.93 h60
  text "TID #:" at 726,-1746.27 h60
  text ".TID" at 1271.5,-1746.27 h60
  text "PLOT NAME =" at -1750.5,-1951.6 h60
  text ".plot_File_Name" at -945,-1951.6 h60
  text "GENERATED    :" at 728,-1951.6 h60
  text ".Print_Date" at 1597.5,-1951.6 h60
  text ".Print_Time" at 2326.5,-1951.6 h60
  text "TEXAS INSTRUMENTS" at 3591,-1951.6 h60
M6 Assembly Bottom:
  lines w10: -1814.5,-1614.6 4787.5,-1614.6 ; -1812.5,-1817.93 4787.5,-1817.93 ; -406.5,-2027.77 -406.5,-1824.93 ; 215.5,-1614.6 215.5,-1411.27 ; 1055.5,-1614.6 1055.5,-1411.27 ; 2322.5,-2021.27 2322.5,-1411.27 ; 3211.5,-2021.27 4787,-2021.27 4787,-1411.27 -1814.5,-1411.27 -1814.5,-2021.27 782.5,-2021.27 4787.5,-2021.27 4787.5,-1411.27
  text "COMPONENTS MARKED 'DNP' SHOULD NOT BE POPULATED." at 4580,-1205.27 h60
  text ".VariantName" at 3536,-1321.27 h60
  text "ASSEMBLY VARIANT:" at 4575,-1321.27 h60
  text ".VersionControl_RevNumber" at -486.5,-1543.43 h60
  text "SVN REV:" at 19.5,-1543.43 h60
  text ".PCB_Rev" at 566,-1543.43 h60
  text "REV:" at 857.5,-1543.43 h60
  text ".PRJ_Number" at 1702,-1543.43 h60
  text "BOARD #:" at 2247.5,-1543.43 h60
  text "PCB VIEWED FROM BOTTOM SIDE" at 4724,-1543.43 h60
  text ".TID" at 1702,-1746.77 h60
  text "TID #:" at 2247.5,-1746.77 h60
  text "TEXAS INSTRUMENTS" at -617.5,-1952.1 h60
  text ".Print_Time" at 647,-1952.1 h60
  text ".Print_Date" at 1376,-1952.1 h60
  text "GENERATED    :" at 2245.5,-1952.1 h60
  text ".plot_File_Name" at 3918.5,-1952.1 h60
  text "PLOT NAME =" at 4724,-1952.1 h60
M9 Title Sheet:
  drawing of 57 lines, arcs and shapes, not listed
  text "1" at -782.16,7149.23 h70
  text "2" at 1713.5,7149.23 h70
  text "3" at 4202.84,7149.23 h70
  text "4" at 6709.51,7149.23 h70
  text "5" at 9208.5,7149.23 h70
  text "6" at 11713.5,7149.23 h70
  text "A" at -1938.5,6006.23 h70
  text "A" at 12861.5,6006.23 h70
  text "B" at -1938.5,3626.23 h70
  text "B" at 12861.5,3626.23 h70
  text "C" at -1938.5,1251.23 h70
  text "C" at 12861.5,1251.23 h70
  text "PROJECT TITLE:" at 9821.5,-609.77 h45
  text ".PRJ_Title" at 9871.5,-743.09 h70
  text "DESIGNED FOR:" at 9821.5,-910.77 h45
  text ".PRJ_Customer" at 9871.5,-1050.77 h70
  text "D" at -1938.5,-1118.77 h70
  text "D" at 12861.5,-1118.77 h70
  text "FILE NAME:" at 9821.5,-1210.77 h45
  text ".PCB_File_Name_No_Path" at 9871.5,-1330.77 h70
  text "Texas Instruments (TI) and/or its licensors do not warrant the accuracy or completeness of this specification" at 4852,-1492.61 h45
  text "ENGINEER:" at 9821.5,-1500.77 h45
  text "LAYOUT BY:" at 11326.5,-1500.77 h45
  text "or any information contained therein. TI and/or its licensors do not warrant that this design will meet" at 4807.01,-1605.27 h45
  text ".PRJ_Engineer" at 9871.5,-1655.76 h70
  text ".PCB_Layout" at 11377,-1655.76 h70
  text "the specifications, will be suitable for your application or fit for any particular purpose, or will operate in" at 4807.01,-1717.94 h45
  text ".Layer_Name" at -945,-1745.76 h60
  text "ALTIUM DESIGNER VERSION:" at 11326.5,-1810.77 h45
  text "an implementation. TI and/or its licensors do not warrant that the design is production worthy. You should" at 4807.01,-1830.6 h45
  text "completely validate and test your design implementation to confirm the system functionality for your application." at 4852,-1943.27 h45
  text ".print_Scale" at 9871.5,-1944.09 h70
  text ".Application_BuildNumber" at 11377,-1944.09 h70
  text "1" at -782.16,-2150.77 h70
  text "2" at 1713.5,-2150.77 h70
  text "3" at 4202.84,-2150.77 h70
  text "4" at 6709.51,-2150.77 h70
  text "5" at 9208.5,-2150.77 h70
  text "6" at 11713.5,-2150.77 h70
M10 Fab Notes:
  drawing of 189 lines, arcs and shapes, not listed
  text "DESIGN INFORMATION" at 10860.02,5468.91 h60
  text "MIN. TRACK WIDTH:" at 10215.46,5336.78 h60
  text "8" at 11311.7,5336.78 h60
  text "MIL" at 11466.46,5336.78 h60
  text "7.874" at 11145.32,5215.09 h60
  text "MIN. CLEARANCE:" at 10215.46,5212.65 h60
  text "MIL" at 11466.46,5212.65 h60
  text "MIN. VIA PAD SIZE:" at 10215.46,5088.53 h60
  text "24" at 11281.71,5088.53 h60
  text "MIL" at 11466.46,5088.53 h60
  text "0.05mm (2MIL)" at 10910.46,4958.63 h60
  text "MINIMUM ANNULAR RING" at 9886.23,4950.41 h60
  text "EXTERNAL" at 11618.46,4950.41 h60
  text "PER" at 10086.23,4840.28 h60
  text "IPC-D-275 CLASS 2 LEVEL C" at 10306.23,4840.28 h60
  text "MIL, HOLES" at 11794.46,4739.8 h60
  text "+/-" at 11402,4731.22 h60
  text "+/-" at 12256,4731.22 h60
  text "REGISTRATION TOLERANCES:" at 9886.23,4730.15 h60
  text "METAL" at 11086,4730.15 h60
  text "5" at 11662.2,4730.15 h60
  text "3" at 12495.2,4730.15 h60
  text "MIL" at 12611.46,4730.15 h60
  text "HOLE SIZE TOLERANCE (UNLESS OTHERWISE SPECIFIED):" at 9886.23,4631.84 h60
  text "+/-" at 12256,4628.96 h60
  text "3" at 12495.2,4627.9 h60
  text "MIL" at 12611.46,4627.9 h60
  text "MATERIAL:" at 9811.46,4490.25 h60
  text "FR-4 High Tg" at 10797.9,4361.73 h60
  text "X" at 10653.46,4353.74 h60
  text "FR-408" at 10232.46,4349.22 h60
  text "OTHER" at 11720.46,4349.22 h60
  text "62 MIL (1.6mm) +/-10%" at 10552.56,4206.19 h60
  text "X" at 10432.46,4203.74 h60
  text "THICKNESS:" at 9886.23,4197.97 h60
  text "OTHER" at 11837.46,4197.97 h60
  text "TOLERANCE:" at 9886.23,4059.65 h60
  text "X" at 10734.46,4059.65 h60
  text "ANSI IPC-6012 TYPE 3 CLASS 2" at 10912.48,4059.65 h60
  text "OTHER +/-" at 10912.46,3915.47 h60
  text "BOW & TWIST:" at 9886.23,3770.28 h60
  text "X" at 10734.46,3770.28 h60
  text "ANSI IPC-6012 TYPE 3 CLASS 2" at 10912.48,3770.28 h60
  text "OTHER +/-" at 10912.46,3623.58 h60
  text "DRILLING:" at 9811.46,3492.96 h60
  text "NC_DRILL FILES" at 11572.46,3387.77 h60
  text "REFERENCE:" at 9886.23,3383.84 h60
  text "X" at 10543.46,3383.74 h60
  text "AS SHOWN" at 10721.46,3383.84 h60
  text "X" at 11444.46,3383.84 h60
  text "OTHER" at 11870.46,3241.58 h60
  text "PTH COPPER THICKNESS:" at 9885.91,3238.06 h60
  text "X" at 11025.14,3238.06 h60
  text "20-30 um" at 11153.14,3238.06 h60
  text "BOARD FINISH:" at 9811.46,3090.46 h60
  text "SILKSCREEN:" at 9966.68,2980.33 h60
  text "X" at 10924.46,2980.33 h60
  text "TOP" at 11041.46,2980.33 h60
  text "X" at 11434.46,2980.33 h60
  text "BOTTOM" at 11552.46,2980.33 h60
  text "SILKSCREEN COLOR:" at 9966.68,2825.14 h60
  text "X" at 10923.46,2825.14 h60
  text "WHITE" at 11041.46,2825.14 h60
  text "OTHER" at 11552.46,2825.14 h60
  text "X" at 11054.46,2681.69 h60
  text "GREEN" at 11172.46,2681.69 h60
  text "OTHER" at 11790.46,2681.69 h60
  text "SOLDER RESIST COLOR:" at 9966.68,2674.83 h60
  text "X" at 11054.46,2527.44 h60
  text "MATTE" at 11172.46,2527.44 h60
  text "SEMI-GLOSS" at 11790,2526.8 h60
  text "IMMERSION GOLD (ENIG)" at 10872.46,2354.67 h60
  text "ENEPIG" at 12210,2347.45 h60
  text "SURFACE FINISH:" at 9811.46,2346.45 h60
  text "X" at 10694.46,2346.45 h60
  text "IMM. TIN/SILVER OR EQUIV" at 10141,2209.13 h60
  text "OTHER" at 11572.46,2205.2 h60
  text "ARRAY/PANEL:" at 9811.46,2049.82 h60
  text "CUT AND TRIM PER M1 BOARD OUTLINE" at 10872.46,2041.6 h60
  text "N.C. ROUTE" at 10872.46,1905.63 h60
  text "X" at 11560.46,1905.63 h60
  text "V. SCORE" at 11738.46,1905.63 h60
  text "CERTIFICATION:" at 9811.46,1776.5 h60
  text "MATERIALS AND WORKMANSHIP FOR ALL PCBS" at 10536.46,1776.5 h60
  text "TO MEET OR EXCEED THE REQUIREMENTS OF:" at 10536.46,1682.44 h60
  text "X" at 10173.97,1553.81 h60
  text "ANSI IPC-A-600F CLASS ->" at 10301.96,1553.81 h60
  text "X" at 11949.97,1553.81 h60
  text "2" at 12059.96,1553.81 h60
  text "1" at 11744.96,1552.32 h60
  text "3" at 12413.96,1552.32 h60
  text "X" at 10985.97,1406.13 h60
  text "RoHS" at 11113.96,1406.13 h60
  text "OTHER" at 11758.36,1406.13 h60
  text "PER ORDER" at 12155.42,1406.13 h60
  text "ALL BOARDS MUST MEET OR EXCEED UL94-V0 REQUIREMENTS." at 9839,1252.3 h60
  text "PCB MUST BEAR THE UL94V-0 UL REGISTERED MATERIAL ID NUMBER" at 9839,1136.24 h60
  text "ADDITIONAL REQUIREMENTS:" at 9811.46,966.81 h60
  text "MICROSECTION:" at 9886.23,859.69 h60
  text "YES" at 10791.96,859.69 h60
  text "REQUIRED" at 11653.46,715.35 h60
  text "BARE BOARD ELEC. TEST:" at 9886.23,712.5 h60
  text "NONE" at 11191.96,712.5 h60
  text "X" at 11535.46,712.5 h60
  text "PER ORDER" at 12245.46,712.5 h60
  text "XX MIL VIAS REQUIRE NON-CONDUCTIVE FILL AND PLANARIZE" at 10054.38,507.55 h59
  text "XX MIL VIAS REQUIRE CONDUCTIVE FILL AND PLANARIZE" at 10062.38,403.58 h60
  text "OUTER XX MIL TRACES REQUIRE 50 OHM SINGLE-ENDED IMPEDANCE" at 10061.39,240.19 h58
  text "LAYER 2 & 3 (INNER LAYERS) XX MIL WIDE, XX MIL SPACE / TRACES REQUIRE 100 OHM DIFFERENTIAL IMPEDANCE" at 10053.39,4.48 h60
  text ".Layer_Name" at -945,-1745.76 h60
M11 Gerber Information:
  lines w10: -1814,-1817.43 4786,-1817.43 ; -1814,-1614.1 4788,-1614.1 ; -1814,-1410.77 -1814,-2020.77 2191,-2020.77 4788,-2020.77 4788,-1410.77 -1813.5,-1410.77 -1813.5,-2020.77 -238,-2020.77 ; 651,-2020.77 651,-1410.77 ; 1918,-1614.1 1918,-1410.77 ; 2758,-1614.1 2758,-1410.77 ; 3380,-2027.27 3380,-1824.43
  text "ALL ARTWORK VIEWED FROM TOP SIDE" at -1750.5,-1542.93 h60
  text "BOARD #:" at 726,-1542.93 h60
  text ".PRJ_Number" at 1271.5,-1542.93 h60
  text "REV:" at 2116,-1542.93 h60
  text ".PCB_Rev" at 2407.5,-1542.93 h60
  text "SVN REV:" at 2954,-1542.93 h60
  text ".VersionControl_RevNumber" at 3460,-1542.93 h60
  text "LAYER NAME =" at -1750.5,-1745.76 h60
  text "TID #:" at 726,-1746.27 h60
  text ".TID" at 1271.5,-1746.27 h60
  text "PLOT NAME =" at -1750.5,-1951.6 h60
  text ".plot_File_Name" at -945,-1951.6 h60
  text "GENERATED    :" at 728,-1951.6 h60
  text ".Print_Date" at 1597.5,-1951.6 h60
  text ".Print_Time" at 2326.5,-1951.6 h60
  text "TEXAS INSTRUMENTS" at 3591,-1951.6 h60
M12 Stackup:
  drawing of 191 lines, arcs and shapes, not listed
  text "Layer" at 8299.59,6987.67 h60
  text "Name" at 8709.51,6987.67 h60
  text "Material" at 9639.25,6987.67 h60
  text "Thickness" at 10499.02,6987.67 h60
  text "Constant" at 11148.85,6987.67 h60
  text "Board Layer Stack" at 11718.71,6987.67 h60
  text "Top Overlay" at 8709.51,6867.67 h60
  text "Top Solder" at 8709.51,6747.67 h60
  text "Solder Resist" at 9639.25,6747.67 h60
  text "0.40mil" at 10499.02,6747.67 h60
  text "3.5" at 11148.85,6747.67 h60
  text "1" at 8299.59,6627.67 h60
  text "Top Layer" at 8709.51,6627.67 h60
  text "1.40mil" at 10499.02,6627.67 h60
  text "Dielectric1" at 8709.51,6507.67 h60
  text "FR-4 High Tg" at 9639.25,6507.67 h60
  text "59.20mil" at 10499.02,6507.67 h60
  text "4.8" at 11148.85,6507.67 h60
  text "2" at 8299.59,6387.67 h60
  text "Bottom Layer" at 8709.51,6387.67 h60
  text "1.40mil" at 10499.02,6387.67 h60
  text "Bottom Solder" at 8709.51,6267.67 h60
  text "Solder Resist" at 9639.25,6267.67 h60
  text "0.40mil" at 10499.02,6267.67 h60
  text "3.5" at 11148.85,6267.67 h60
  text "Bottom Overlay" at 8709.51,6147.67 h60
  text ".Layer_Name" at -945,-1745.76 h60
M13 Component Bodies Top:
  text ".Layer_Name" at -945,-1745.76 h60
M14 Component Bodies Bottom:
  text ".Layer_Name" at -945,-1745.76 h60
M15 Courtyards Top:
  text ".Layer_Name" at -945,-1745.76 h60
M16 Courtyards Bottom:
  text ".Layer_Name" at -945,-1745.76 h60
Drill Drawing:
  circle w10: c3841.72,2403.01 r27.63
  lines w10: 3814.09,1933.36 3869.34,1933.36 3841.72,1878.11 3814.09,1933.36 ; 3814.09,2016.24 3827.9,2016.24 3827.9,2002.43 3855.53,2002.43 3855.53,2016.24 3869.34,2016.24 3869.34,2043.87 3855.53,2043.87 3855.53,2057.68 3827.9,2057.68 3827.9,2043.87 3814.09,2043.87 3814.09,2016.24 ; 3814.09,2126.75 3869.34,2126.75 3869.34,2182 3814.09,2182 3814.09,2126.75 ; 3814.09,2251.07 3841.72,2264.88 3869.34,2251.07 3855.53,2278.7 3869.34,2306.32 3841.72,2292.51 3814.09,2306.32 3827.9,2278.7 3814.09,2251.07
  lines w12: 3764,1840.81 6995.49,1840.81 ; 3764,2462.41 6995.49,2462.41 ; 4101.86,1716.49 4101.86,2586.73 ; 4433.86,1716.49 4433.86,2586.73 ; 5070.43,1716.49 5070.43,2586.73 ; 5329.57,1716.49 5329.57,2586.73 ; 5704.72,1716.49 5704.72,2586.73 ; 6429.05,1716.49 6429.05,2586.73 ; 3764,1716.49 6995.49,1716.49 6995.49,2586.73 3764,2586.73 3764,1716.49
  text "Symbol" at 3838.59,2499.71 h72
  text "Quantity" at 4139.16,2499.71 h72
  text "Finished Hole Size" at 4471.16,2499.71 h72
  text "Plated" at 5107.72,2499.71 h72
  text "Hole Type" at 5366.86,2499.71 h72
  text "Drill Layer Pair" at 5742.02,2499.71 h72
  text "Hole Tolerance" at 6466.35,2499.71 h72
  text "2" at 4139.16,2375.39 h60
  text "50.00mil (1.270mm)" at 4471.16,2375.39 h60
  text "NPTH" at 5107.72,2375.39 h60
  text "Round" at 5366.86,2375.39 h60
  text "Top Layer - Bottom Layer" at 5742.02,2375.39 h60
  text "25" at 4139.16,2251.07 h60
  text "10.00mil (0.254mm)" at 4471.16,2251.07 h60
  text "PTH" at 5107.72,2251.07 h60
  text "Round" at 5366.86,2251.07 h60
  text "Top Layer - Bottom Layer" at 5742.02,2251.07 h60
  text "46" at 4139.16,2126.75 h60
  text "27.56mil (0.700mm)" at 4471.16,2126.75 h60
  text "PTH" at 5107.72,2126.75 h60
  text "Round" at 5366.86,2126.75 h60
  text "Top Layer - Bottom Layer" at 5742.02,2126.75 h60
  text "38" at 4139.16,2002.43 h60
  text "31.50mil (0.800mm)" at 4471.16,2002.43 h60
  text "PTH" at 5107.72,2002.43 h60
  text "Round" at 5366.86,2002.43 h60
  text "Top Layer - Bottom Layer" at 5742.02,2002.43 h60
  text "2" at 4139.16,1878.11 h60
  text "33.07mil (0.840mm)" at 4471.16,1878.11 h60
  text "PTH" at 5107.72,1878.11 h60
  text "Round" at 5366.86,1878.11 h60
  text "Top Layer - Bottom Layer" at 5742.02,1878.11 h60
  text "113 Total" at 4139.16,1753.79 h60
  text ".Layer_Name" at -945,-1745.76 h60
M17 Embedded Cavity:
  text ".Layer_Name" at -945,-1745.76 h60
M18 Embedded Assembly:
  text ".Layer_Name" at -945,-1745.76 h60
M19 Embedded Keepout:
  text ".Layer_Name" at -945,-1745.76 h60

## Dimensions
-1522,-1287.27 to -522,-1287.27 on M2 Board Dimensions
0,0 to 0,2165.35 on M2 Board Dimensions
0,1322.83 to 2755.91,2165.35 on M2 Board Dimensions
